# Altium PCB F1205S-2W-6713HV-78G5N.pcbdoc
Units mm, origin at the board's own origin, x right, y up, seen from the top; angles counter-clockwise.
Board outline 18.8 x 13 mm, 2 copper layers (Top Layer, Bottom Layer), stack 0.78 mm thick; 12 components, 10 nets, 33 pads, 13 vias.
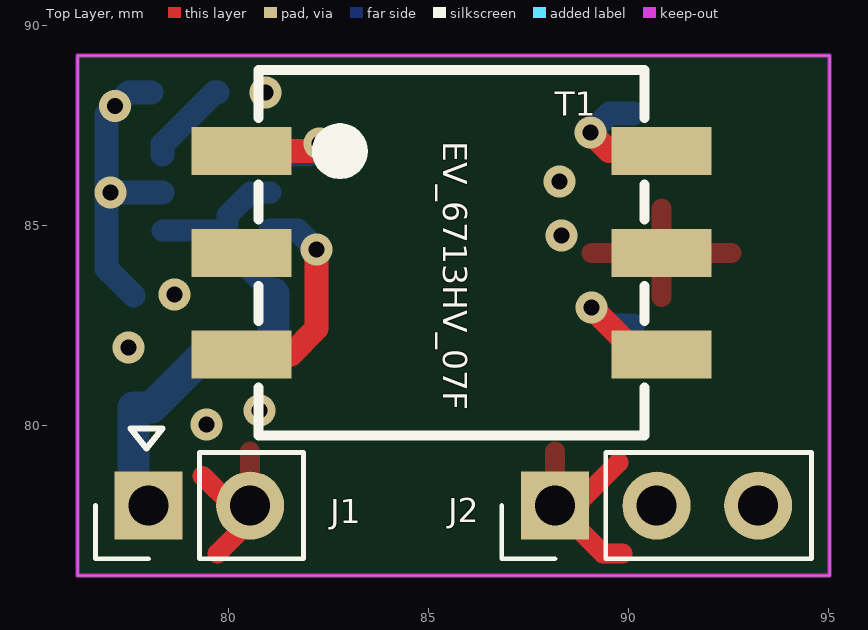
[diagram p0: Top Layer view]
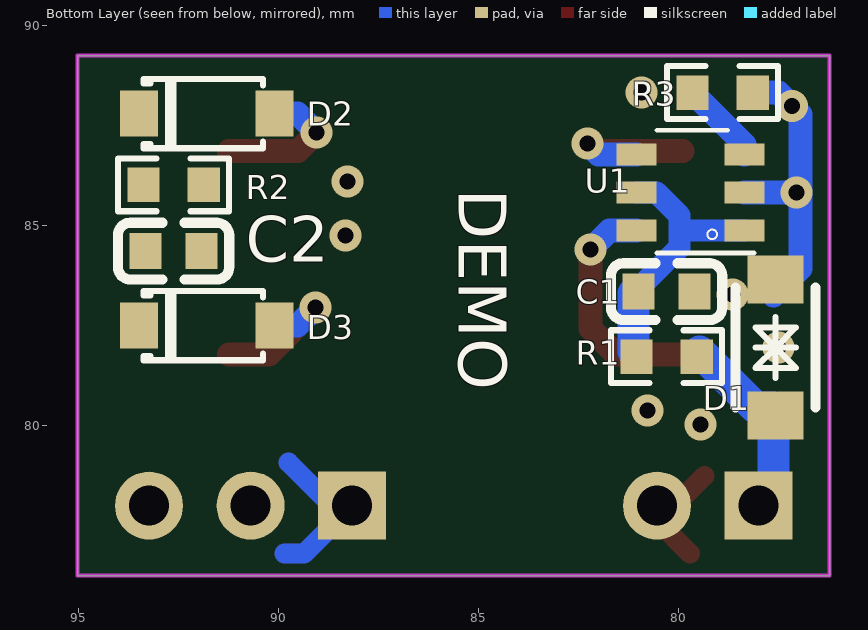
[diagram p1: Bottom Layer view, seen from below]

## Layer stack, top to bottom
Top Solder Mask Layer: solder mask 0.01, Dk 3.3
Top Layer: signal copper 0.035
Dielectric1: surface 0.71, FR4, Dk 4.5
Bottom Layer: signal copper 0.035
Bottom Solder Mask Layer: solder mask 0.01, Dk 3.3

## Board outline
76.225,89.25 95.025,89.25 95.025,76.25 76.225,76.25

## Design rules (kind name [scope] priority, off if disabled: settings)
BoardOutlineClearance safeClearance [All] p0: genericclearance=0.254 ignorepadtopadclearanceinfootprint=FALSE except(0: Arc-SplitContinuation Track-SplitContinuation SMDPad-SplitContinuation THPad-SplitContinuation Via-SplitContinuation Fill-SplitContinuation Poly-SplitContinuation Region-SplitContinuation Text-SplitContinuation)
BoardOutlineClearance Plane_innerPlane [All] p0: genericclearance=0.254 ignorepadtopadclearanceinfootprint=FALSE except(0: Arc-SplitContinuation Track-SplitContinuation SMDPad-SplitContinuation THPad-SplitContinuation Via-SplitContinuation Fill-SplitContinuation Poly-SplitContinuation Region-SplitContinuation Text-SplitContinuation)
BoardOutlineClearance Copper_CopperRegion [All] p0: genericclearance=0.254 ignorepadtopadclearanceinfootprint=FALSE except(0: Arc-SplitContinuation Track-SplitContinuation SMDPad-SplitContinuation THPad-SplitContinuation Via-SplitContinuation Fill-SplitContinuation Poly-SplitContinuation Region-SplitContinuation Text-SplitContinuation)
BoardOutlineClearance Copper_CopperRegion1 [All] p0: genericclearance=0.254 ignorepadtopadclearanceinfootprint=FALSE except(0: Arc-SplitContinuation Track-SplitContinuation SMDPad-SplitContinuation THPad-SplitContinuation Via-SplitContinuation Fill-SplitContinuation Poly-SplitContinuation Region-SplitContinuation Text-SplitContinuation)
BoardOutlineClearance Copper_CopperRegion2 [All] p0: genericclearance=0.254 ignorepadtopadclearanceinfootprint=FALSE except(0: Arc-SplitContinuation Track-SplitContinuation SMDPad-SplitContinuation THPad-SplitContinuation Via-SplitContinuation Fill-SplitContinuation Poly-SplitContinuation Region-SplitContinuation Text-SplitContinuation)
BoardOutlineClearance Copper_CopperRegion3 [All] p0: genericclearance=0.254 ignorepadtopadclearanceinfootprint=FALSE except(0: Arc-SplitContinuation Track-SplitContinuation SMDPad-SplitContinuation THPad-SplitContinuation Via-SplitContinuation Fill-SplitContinuation Poly-SplitContinuation Region-SplitContinuation Text-SplitContinuation)
BoardOutlineClearance Copper_CopperRegion4 [All] p0: genericclearance=0.254 ignorepadtopadclearanceinfootprint=FALSE except(0: Arc-SplitContinuation Track-SplitContinuation SMDPad-SplitContinuation THPad-SplitContinuation Via-SplitContinuation Fill-SplitContinuation Poly-SplitContinuation Region-SplitContinuation Text-SplitContinuation)
BoardOutlineClearance Copper_copperRegion1 [All] p0: genericclearance=0.254 ignorepadtopadclearanceinfootprint=FALSE except(0: Arc-SplitContinuation Track-SplitContinuation SMDPad-SplitContinuation THPad-SplitContinuation Via-SplitContinuation Fill-SplitContinuation Poly-SplitContinuation Region-SplitContinuation Text-SplitContinuation)
BoardOutlineClearance otherClearance [All] p0: genericclearance=0.254 ignorepadtopadclearanceinfootprint=FALSE except(0: Arc-SplitContinuation Track-SplitContinuation SMDPad-SplitContinuation THPad-SplitContinuation Via-SplitContinuation Fill-SplitContinuation Poly-SplitContinuation Region-SplitContinuation Text-SplitContinuation)
Clearance safeClearance [All] p1: gap=0.178 ignorepadtopadclearanceinfootprint=FALSE
Clearance Plane_innerPlane [All] p1: gap=0.178 ignorepadtopadclearanceinfootprint=FALSE
Clearance Copper_CopperRegion [All] p1: gap=0.178 ignorepadtopadclearanceinfootprint=FALSE
Clearance Copper_CopperRegion1 [All] p1: gap=0.178 ignorepadtopadclearanceinfootprint=FALSE
Clearance Copper_CopperRegion2 [All] p1: gap=0.178 ignorepadtopadclearanceinfootprint=FALSE
Clearance Copper_CopperRegion3 [All] p1: gap=0.178 ignorepadtopadclearanceinfootprint=FALSE
Clearance Copper_CopperRegion4 [All] p1: gap=0.178 ignorepadtopadclearanceinfootprint=FALSE
Clearance Copper_copperRegion1 [All] p1: gap=0.178 ignorepadtopadclearanceinfootprint=FALSE
Clearance otherClearance [All] p1: gap=0.178 ignorepadtopadclearanceinfootprint=FALSE
DiffPairsRouting differentialPair [All] p1: maxuncoupledlength=10 minlimit=5.9843 maxlimit=Infinity mostfreqgap=5.9843 toplayer_minwidth=5 toplayer_prefwidth=10 toplayer_maxwidth=100 bottomlayer_minwidth=5 bottomlayer_prefwidth=10 bottomlayer_maxwidth=100
PasteMaskExpansion Common [All] p1: expansion=0
PlaneConnect innerPlane [All] p1: planeconnectstyle=Relief reliefexpansion=0.508 reliefentries=4 reliefconductorwidth=0.254 reliefairgap=0.254
PolygonConnect CopperRegion [All] p1: connectstyle=Relief reliefentries=4 reliefconductorwidth=19.685 polygonreliefangle="90 Angle" airgapwidth=19.685
PolygonConnect CopperRegion1 [All] p1: connectstyle=Direct reliefentries=4 reliefconductorwidth=10 polygonreliefangle="90 Angle" airgapwidth=10
PolygonConnect CopperRegion2 [All] p1: connectstyle=Direct reliefentries=4 reliefconductorwidth=10 polygonreliefangle="90 Angle" airgapwidth=10
PolygonConnect CopperRegion3 [All] p1: connectstyle=Relief reliefentries=4 reliefconductorwidth=0 polygonreliefangle="90 Angle" airgapwidth=0.9843
PolygonConnect CopperRegion4 [All] p1: connectstyle=Relief reliefentries=4 reliefconductorwidth=0 polygonreliefangle="90 Angle" airgapwidth=0.9843
PolygonConnect copperRegion1 [All] p1: connectstyle=Relief reliefentries=4 reliefconductorwidth=10 polygonreliefangle="90 Angle" airgapwidth=10
RoutingVias viaSize [All] p1: viastyle="Through Hole" holewidth=12.0078 minholewidth=11.811 maxholewidth=236.1812 width=12.0078 minwidth=11.811 maxwidth=236.1812
SolderMaskExpansion Common [All] p1: useseparateexpansions=TRUE expansion=0 expansionbottom=0
Width trackWidth [All] p1: maxlimit=100 minlimit=5 preferedwidth=10

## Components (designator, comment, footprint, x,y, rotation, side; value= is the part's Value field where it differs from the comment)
C1 "" C0603 80.3,83.35 r0 bottom
C2 "" C0603 92.625,84.362 r0 bottom
D1 "" SOD-123FL_L2.8-W1.8-LS3.7-BI 77.575,81.95 r90 bottom
D2 "" SOD-123_L2.8-W1.8-LS3.7-RD 91.8,87.8 r180 bottom
D3 "" SOD-123_L2.8-W1.8-LS3.7-RD 91.8,82.5 r180 bottom
J1 "" Connector_JST:JST_PH_B2B-PH-K_1x02_P2.00mm_Vertical 78,78 r90 top
J2 "" Connector_PinHeader_2.54mm:PinHeader_1x03_P2.54mm_Vertical 88.16,78 r90 top
R1 "" R0603 80.3,81.723 r0 bottom
R2 "" R0603 92.625,86.018 r180 bottom
R3 "" R0603 78.9,88.325 r180 bottom
T1 "" SMD-6_L9.7-W8.9-P2.54-LS12.8-TL 85.575,84.321 r0 top
U1 "" SOT-23-6_L2.9-W1.6-P0.95-LS2.8-BR 79.542,85.796 r0 bottom

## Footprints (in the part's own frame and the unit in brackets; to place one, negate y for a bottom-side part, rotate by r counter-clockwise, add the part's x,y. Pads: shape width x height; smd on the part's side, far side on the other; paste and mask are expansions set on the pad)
C0603 [mm]
  rect 0.8x0.9 smd: 1(-0.7,0) 2(0.7,0)
  silkscreen extent -1.39,-0.71 1.39,0.71
Connector_JST:JST_PH_B2B-PH-K_1x02_P2.00mm_Vertical [mm]
  rect 1.7x1.7 hole 1: 1(0,0)
  round 1.7 hole 1: 2(0,-2.54)
  silkscreen extent -1.33,-3.87 1.33,1.33
Connector_PinHeader_2.54mm:PinHeader_1x03_P2.54mm_Vertical [mm]
  rect 1.7x1.7 hole 1: 5(0,0)
  round 1.7 hole 1: 6(0,-2.54) 7(0,-5.08)
  silkscreen extent -1.33,-6.41 1.33,1.33
R0603 [mm]
  rect 0.806x0.864 smd: 1(-0.753,0) 2(0.753,0)
  silkscreen extent -1.39,-0.66 1.39,0.66
SMD-6_L9.7-W8.9-P2.54-LS12.8-TL [mm]
  rect 2.5x1.2 smd: 1(-5.25,2.54) 2(-5.25,0) 3(-5.25,-2.54) 4(5.25,-2.54) 5(5.25,0) 6(5.25,2.54)
  silkscreen extent -4.83,-4.57 4.83,4.57
SOD-123_L2.8-W1.8-LS3.7-RD [mm]
  rect 0.95x1.15 smd: 1(-1.692,0) 2(1.692,0)
  silkscreen extent -1.58,-0.87 1.41,0.87
SOD-123FL_L2.8-W1.8-LS3.7-BI [mm]
  rect 1.2x1.4 smd: 1(-1.7,0) 2(1.7,0)
  silkscreen extent -1.5,-1 1.5,1
SOT-23-6_L2.9-W1.6-P0.95-LS2.8-BR [mm]
  rect 1x0.55 smd: 1(-1.192,0.921) 2(-1.192,-0.029) 3(-1.192,-0.979) 4(1.508,-0.979) 5(1.508,-0.029) 6(1.508,0.921)
  silkscreen extent -1.43,-1.59 1,1.48

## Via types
v1: diameter 0.8, hole 0.4, Top Layer to Bottom Layer, 13 vias

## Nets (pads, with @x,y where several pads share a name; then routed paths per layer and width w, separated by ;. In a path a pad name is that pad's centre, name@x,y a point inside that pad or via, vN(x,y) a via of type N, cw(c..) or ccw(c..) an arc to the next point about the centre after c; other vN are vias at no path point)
0V: C2.1 J2.5 R2.2 T1.5 | length 8.6
  Top Layer w0.5: J2.5@88.775,78 J2.5@88.675,78 ; 89.75,79.075 J2.5@88.675,78 ; 89.85,76.801 89.359,76.801 J2.5 J2.5@88.675,78
  Bottom Layer w0.5: J2.5@88.375,77.925 J2.5@88.375,78 ; J2.5@88.375,78.025 J2.5@88.375,78 ; 89.75,79.075 88.675,78 J2.5@88.375,78 ; 89.85,76.801 89.359,76.801 J2.5 J2.5@88.375,78
  other v1: 88.325,84.75 88.275,86.1
$1N9: D2.2 T1.6 | length 3.6
  Top Layer w0.6: v1(89.05,87.325) 89.514,86.861 T1.6@91.245,86.861
  Bottom Layer w0.6: v1(89.05,87.325) 89.525,87.8 D2.2
$1N15: D3.2 T1.4 | length 3.9
  Top Layer w0.6: v1(89.075,82.95) 90.244,81.781 T1.4@91.245,81.781
  Bottom Layer w0.6: v1(89.075,82.95) 89.525,82.5 D3.2
+VO: C2.2 D2.1 D3.1 J2.7 R2.1
CLK: R3.1 U1.3 | length 2.2
  Bottom Layer w0.6: U1.3 78.35,87.025 79.65,88.325 R3.1@79.725,88.325
GND: C1.1 D1.2 J1.2 R3.2 U1.2 | length 10.6
  Top Layer w0.5: 79.35,78.745 80.095,78 J1.2 80.54,77.625 79.72,76.805
  Bottom Layer w0.6: D1.2@77.625,83.25 76.95,83.925 v1@76.95,85.8 ; R3.2@78.075,88.325 77.5,88.325 v1(77.162,87.987) 76.95,87.775 v1@76.95,85.8 ; U1.2 v1(77.05,85.825) 76.975,85.825 v1@76.95,85.8
  other v1: 79.45,80.025 80.775,80.375 77.5,81.95 78.65,83.275 80.925,88.325
VCC: C1.2 R1.2 U1.1 U1.5 | length 6.8
  Bottom Layer w0.55: C1.2@81.025,83.35 81.075,83.35 79.975,84.45 79.975,84.815 79.975,85.25 80.55,85.825 U1.5
  Bottom Layer w0.551: U1.1 79.915,84.875 79.975,84.815
  Bottom Layer w0.8: R1.2@81.125,81.85 C1.2@81.125,83.3
VD1: T1.3 U1.6 | length 5.9
  Top Layer w0.6: T1.3@79.905,81.781 81.558,81.781 82.2,82.423 v1(82.2,84.4)
  Bottom Layer w0.6: U1.6 81.725,84.875 v1(82.2,84.4)
VD2: T1.1 U1.4 | length 3.8
  Top Layer w0.6: T1.1@79.905,86.861 82.086,86.861 v1(82.275,87.05)
  Bottom Layer w0.6: U1.4 82,86.775 v1(82.275,87.05)
VIN: D1.1 J1.1 R1.1 | length 5
  Bottom Layer w0.8: J1.1 77.625,78.375 77.625,80.45 78.075,80.45 R1.1@79.475,81.85
pads on no net: J2.6 T1.2

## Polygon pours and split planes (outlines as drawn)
+VO on Bottom Layer (solid, remove dead copper, pour order 4): 92.75,88.95 94.65,88.95 94.65,76.25 92.75,76.275
0V on Top Layer (solid, remove dead copper, pour order 0): 95.014,89.25 87.575,89.25 87.525,76.25 95.039,76.25
0V on Bottom Layer (solid, remove dead copper, pour order 6): 95.016,89.25 87.575,89.25 87.525,76.25 95.041,76.25
GND on Top Layer (solid, remove dead copper, pour order 2): 76.225,89.225 81.6,89.25 81.625,76.25 76.225,76.25
GND on Bottom Layer (solid, remove dead copper, pour order 8): 76.225,89.225 81.6,89.25 81.625,76.25 76.225,76.25

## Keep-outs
Board Outline Layer:
  the board outline again, w0.1

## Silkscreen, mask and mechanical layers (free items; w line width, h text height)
Top Silkscreen Layer:
  lines w0.15: 77.55,79.925 78.35,79.925 77.95,79.425 77.55,79.925
  text "EV_6713HV_07F" at 85.364,87.111 h0.6 r270
Bottom Silkscreen Layer:
  text "DEMO" at 85.5,85.925 h1.2 r90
